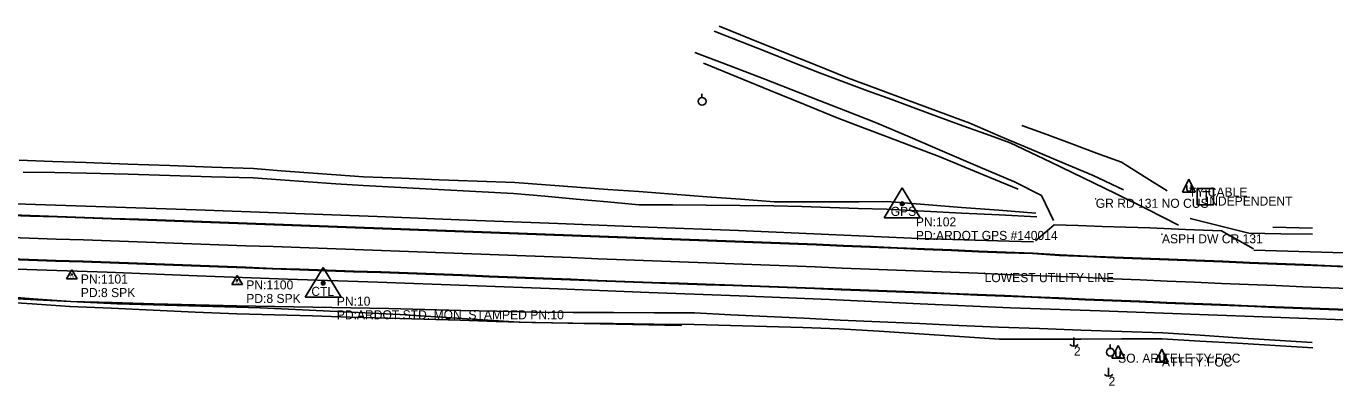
# Model space of a CAD drawing. Extents: x 878399 to 889864, y 1564003 to 1567413.
# Drawn here: x 887438 to 888162, y 1564366 to 1564564 of the extents above; entities that cross this region are included whole.
import ezdxf

# ---------------------------------------------------------------- set-up
doc = ezdxf.new("R2010")
doc.units = 0
for name, color, linetype in [('S_DITCHLINE', 7, 'Continuous'), ('S_DRIVEWAY', 7, 'Continuous'), ('S_EDGE_PAVEMENT', 7, 'Continuous'), ('S_ELECTRIC_UTILITIES_ANNOT', 7, 'Continuous'), ('S_FIBER_OPTIC_CABLE', 7, 'Continuous'), ('S_GRAVEL_ROAD', 7, 'Continuous'), ('S_MSC_PT_SYM', 7, 'Continuous'), ('S_PAVEMENT_CROWN', 7, 'Continuous'), ('S_PRIMARY_CTL', 7, 'Continuous'), ('S_PRIMARY_CTL_ANNOT', 7, 'Continuous'), ('S_SECONDARY_CTL', 7, 'Continuous'), ('S_SECONDARY_CTL_ANNOT', 7, 'Continuous'), ('S_SHOULDER', 7, 'Continuous'), ('S_SURVEY_TEXT_ANNOT', 7, 'Continuous'), ('S_TELEPHONE_UTILITIES', 7, 'Continuous'), ('S_TELEPHONE_UTILITIES_ANNOT', 7, 'Continuous'), ('S_UTILITY_POLE', 7, 'Continuous'), ('S_UTILITY_POLE_ANNOT', 7, 'Continuous'), ('S_UTL_PT_SYM', 7, 'Continuous')]:
    doc.layers.add(name, color=color, linetype=linetype)

msp = doc.modelspace()

# ---------------------------------------------------------------- linework, layer by layer
at = {"layer": 'S_DITCHLINE'}
for points in [[(888045.28, 1564473.95), (888028.58, 1564481.87), (888011.51, 1564489.1), (887994.45, 1564496.33), (887977.38, 1564503.55), (887960.32, 1564510.78), (887943.43, 1564517.06), (887926.53, 1564523.34), (887909.64, 1564529.63), (887892.75, 1564535.91), (887875.01, 1564543.04), (887857.27, 1564550.17), (887839.53, 1564557.3), (887821.79, 1564564.43)], [(887987.13, 1564474.32), (887965.23, 1564483.38), (887943.33, 1564492.43), (887929.25, 1564497.75), (887915.16, 1564503.07), (887901.08, 1564508.39), (887886.99, 1564513.72), (887868.5, 1564521.3), (887850.01, 1564528.88), (887831.51, 1564536.47), (887813.02, 1564544.05)], [(888069.44, 1564473.4), (888056.84, 1564481.33), (888044.24, 1564489.27), (888030.48, 1564494.36), (888016.72, 1564499.46), (888002.96, 1564504.56), (887989.2, 1564509.65)], [(887996.97, 1564461.15), (887976.39, 1564462.74), (887955.8, 1564464.33), (887935.22, 1564465.93), (887914.64, 1564467.52), (887899.07, 1564467.48), (887883.5, 1564467.45), (887867.93, 1564467.42), (887852.37, 1564467.39), (887833.62, 1564468.81), (887814.87, 1564470.23), (887796.12, 1564471.65), (887777.37, 1564473.08), (887760.23, 1564474.31), (887743.08, 1564475.55), (887725.94, 1564476.78), (887708.79, 1564478.01), (887687.87, 1564478.83), (887666.95, 1564479.64), (887646.02, 1564480.45), (887625.1, 1564481.26), (887609.89, 1564482.38), (887594.69, 1564483.5), (887579.48, 1564484.61), (887564.28, 1564485.73), (887541.1, 1564486.58), (887517.91, 1564487.43), (887494.73, 1564488.28), (887471.55, 1564489.14), (887453.1, 1564489.78), (887434.65, 1564490.42)], [(887997.43, 1564459.14), (887976.65, 1564460.18), (887955.88, 1564461.21), (887935.11, 1564462.25), (887914.34, 1564463.28), (887898.71, 1564463.77), (887883.08, 1564464.26), (887867.46, 1564464.75), (887851.83, 1564465.24), (887833.22, 1564465.39), (887814.62, 1564465.53), (887796.01, 1564465.68), (887777.4, 1564465.82), (887760.04, 1564467.38), (887742.68, 1564468.94), (887725.32, 1564470.5), (887707.96, 1564472.06), (887687.19, 1564473.13), (887666.42, 1564474.2), (887645.65, 1564475.27), (887624.88, 1564476.34), (887609.65, 1564477.4), (887594.43, 1564478.47), (887579.2, 1564479.53), (887563.98, 1564480.6), (887540.93, 1564481.27), (887517.88, 1564481.95), (887494.83, 1564482.63), (887471.77, 1564483.3), (887454.31, 1564483.52), (887436.85, 1564483.75)], [(888149.84, 1564449.49), (888132.3, 1564449.82), (888114.77, 1564450.16), (888098.52, 1564454.17), (888082.27, 1564458.18)], [(888149.86, 1564452.88), (888127.89, 1564453.46)], [(888150.12, 1564386.83), (888129.29, 1564388.05), (888108.46, 1564389.27), (888087.63, 1564390.49), (888066.79, 1564391.71), (888044.31, 1564391.66), (888021.82, 1564391.61), (887999.34, 1564391.56), (887976.85, 1564391.51), (887954.63, 1564392.96), (887932.41, 1564394.42), (887910.19, 1564395.87), (887887.96, 1564397.32), (887867.96, 1564397.9), (887847.96, 1564398.48), (887827.96, 1564399.07), (887807.96, 1564399.65), (887785.57, 1564399.91), (887763.17, 1564400.17), (887740.77, 1564400.43), (887718.37, 1564400.69), (887698.41, 1564401.32), (887678.45, 1564401.95), (887658.48, 1564402.58), (887638.52, 1564403.2), (887617.64, 1564403.77), (887596.75, 1564404.34), (887575.87, 1564404.91), (887554.98, 1564405.48), (887531.89, 1564406.52), (887508.79, 1564407.57), (887485.7, 1564408.61), (887462.6, 1564409.65), (887441.87, 1564411.02), (887421.14, 1564412.39)], [(888149.76, 1564389.68), (888129.08, 1564391.01), (888108.41, 1564392.34), (888087.73, 1564393.67), (888067.05, 1564394.99), (888044.37, 1564395.79), (888021.68, 1564396.58), (887998.99, 1564397.38), (887976.3, 1564398.17), (887954.38, 1564399.16), (887932.46, 1564400.14), (887910.54, 1564401.13), (887888.62, 1564402.12), (887868.5, 1564403.09), (887848.38, 1564404.07), (887828.26, 1564405.05), (887808.14, 1564406.02), (887785.77, 1564406.12), (887763.39, 1564406.22), (887741.02, 1564406.32), (887718.64, 1564406.42), (887698.72, 1564406.92), (887678.81, 1564407.41), (887658.89, 1564407.91), (887638.97, 1564408.4), (887617.98, 1564408.8), (887596.99, 1564409.2), (887576, 1564409.61), (887555.01, 1564410.01), (887532.03, 1564410.57), (887509.05, 1564411.14), (887486.07, 1564411.71), (887463.1, 1564412.28), (887442.27, 1564413.89), (887421.45, 1564415.51)]]:
    msp.add_lwpolyline(points, dxfattribs=at)
at = {"layer": 'S_DRIVEWAY'}
msp.add_lwpolyline([(888117.21, 1564441.53), (888099.57, 1564451.41), (888079.75, 1564452.18), (888059.93, 1564452.96), (888046.71, 1564453.41), (888033.48, 1564453.87), (888020.26, 1564454.32), (888007.04, 1564454.77), (887996.68, 1564445.93)], dxfattribs=at)
at = {"layer": 'S_EDGE_PAVEMENT'}
for points in [[(887425.87, 1564460.41), (887440.86, 1564459.9), (887455.84, 1564459.36), (887470.82, 1564458.82), (887485.8, 1564458.29), (887500.79, 1564457.76), (887515.77, 1564457.23), (887530.76, 1564456.71), (887545.74, 1564456.18), (887560.73, 1564455.65), (887575.72, 1564455.12), (887590.71, 1564454.57), (887590.71, 1564454.57), (887590.71, 1564454.57), (887605.69, 1564454.01), (887620.68, 1564453.45), (887635.74, 1564452.89), (887635.74, 1564452.89), (887635.74, 1564452.89), (887650.73, 1564452.32), (887665.72, 1564451.75), (887680.71, 1564451.19), (887695.7, 1564450.64), (887710.69, 1564450.09), (887725.68, 1564449.54), (887740.67, 1564448.97), (887755.66, 1564448.4), (887770.65, 1564447.82), (887785.64, 1564447.25), (887800.63, 1564446.7), (887815.62, 1564446.16), (887830.61, 1564445.61), (887830.61, 1564445.61), (887830.61, 1564445.61), (887845.6, 1564445.05), (887860.59, 1564444.49), (887875.58, 1564443.93), (887890.57, 1564443.33), (887905.41, 1564442.69), (887920.39, 1564442.05), (887935.38, 1564441.42), (887935.38, 1564441.42), (887935.38, 1564441.42), (887950.36, 1564440.81), (887965.35, 1564440.2), (887965.35, 1564440.2), (887965.35, 1564440.2), (887980.34, 1564439.59), (887995.33, 1564439.13), (888010.3, 1564438.09), (888025.43, 1564437.47), (888040.41, 1564436.85), (888055.39, 1564436.23), (888070.38, 1564435.66), (888085.36, 1564435.1), (888100.34, 1564434.54), (888115.32, 1564433.92), (888130.31, 1564433.32), (888145.29, 1564432.72), (888160.28, 1564432.13), (888175.26, 1564431.52)], [(887425.59, 1564460.07), (887440.58, 1564459.57), (887455.56, 1564459.03), (887470.54, 1564458.49), (887485.53, 1564457.95), (887500.51, 1564457.43), (887515.5, 1564456.9), (887530.48, 1564456.37), (887545.47, 1564455.84), (887560.46, 1564455.31), (887575.45, 1564454.78), (887590.43, 1564454.23), (887590.43, 1564454.23), (887590.43, 1564454.23), (887605.42, 1564453.68), (887620.41, 1564453.12), (887635.47, 1564452.55), (887635.47, 1564452.55), (887635.47, 1564452.55), (887650.46, 1564451.99), (887665.45, 1564451.42), (887680.44, 1564450.85), (887695.43, 1564450.3), (887710.42, 1564449.75), (887725.41, 1564449.2), (887740.41, 1564448.64), (887755.4, 1564448.06), (887770.39, 1564447.49), (887785.38, 1564446.92), (887800.37, 1564446.37), (887815.36, 1564445.82), (887830.35, 1564445.28), (887830.35, 1564445.28), (887830.35, 1564445.28), (887845.34, 1564444.72), (887860.33, 1564444.16), (887875.32, 1564443.6), (887890.31, 1564442.99), (887905.15, 1564442.36), (887920.14, 1564441.72), (887935.12, 1564441.08), (887935.12, 1564441.08), (887935.12, 1564441.08), (887950.11, 1564440.47), (887965.1, 1564439.87), (887965.1, 1564439.87), (887965.1, 1564439.87), (887980.09, 1564439.26), (887995.08, 1564438.79), (888010.05, 1564437.76), (888025.18, 1564437.13), (888040.16, 1564436.51), (888055.15, 1564435.89), (888070.13, 1564435.32), (888085.11, 1564434.77), (888100.1, 1564434.2), (888115.08, 1564433.58), (888130.06, 1564432.98), (888145.05, 1564432.39), (888160.03, 1564431.8), (888175.02, 1564431.18)], [(887424.76, 1564435.73), (887439.75, 1564435.22), (887454.73, 1564434.72), (887469.71, 1564434.22), (887484.7, 1564433.71), (887499.68, 1564433.15), (887514.67, 1564432.59), (887529.65, 1564432.02), (887544.64, 1564431.46), (887559.62, 1564430.89), (887574.61, 1564430.32), (887589.6, 1564429.79), (887604.59, 1564429.3), (887619.58, 1564428.81), (887634.46, 1564428.32), (887649.45, 1564427.76), (887664.43, 1564427.21), (887679.42, 1564426.65), (887694.41, 1564426.06), (887709.39, 1564425.46), (887724.38, 1564424.86), (887739.37, 1564424.27), (887754.36, 1564423.71), (887769.35, 1564423.14), (887784.34, 1564422.58), (887799.34, 1564422.09), (887814.33, 1564421.59), (887829.32, 1564421.1), (887844.31, 1564420.56), (887859.31, 1564420.01), (887874.3, 1564419.45), (887889.29, 1564418.88), (887904.44, 1564418.28), (887919.42, 1564417.68), (887934.41, 1564417.09), (887949.4, 1564416.5), (887964.39, 1564415.91), (887979.37, 1564415.32), (887979.37, 1564415.32), (887994.36, 1564414.67), (888009.34, 1564414), (888024.1, 1564413.34), (888039.09, 1564412.7), (888054.07, 1564412.1), (888069.05, 1564411.5), (888084.03, 1564410.9), (888099.02, 1564410.3), (888114, 1564409.7), (888128.99, 1564409.11), (888143.97, 1564408.53), (888158.96, 1564407.97), (888173.95, 1564407.4)], [(887425.04, 1564436.06), (887440.03, 1564435.55), (887455.01, 1564435.05), (887469.99, 1564434.55), (887484.98, 1564434.05), (887499.96, 1564433.48), (887514.94, 1564432.92), (887529.93, 1564432.36), (887544.91, 1564431.79), (887559.9, 1564431.23), (887574.88, 1564430.66), (887589.87, 1564430.12), (887604.86, 1564429.63), (887619.85, 1564429.14), (887634.73, 1564428.65), (887649.71, 1564428.1), (887664.7, 1564427.54), (887679.69, 1564426.99), (887694.68, 1564426.4), (887709.66, 1564425.79), (887724.64, 1564425.19), (887739.63, 1564424.61), (887754.62, 1564424.04), (887769.61, 1564423.48), (887784.6, 1564422.92), (887799.6, 1564422.42), (887814.59, 1564421.93), (887829.58, 1564421.44), (887844.57, 1564420.9), (887859.56, 1564420.34), (887874.55, 1564419.79), (887889.54, 1564419.22), (887904.69, 1564418.61), (887919.68, 1564418.02), (887934.67, 1564417.42), (887949.65, 1564416.83), (887964.64, 1564416.24), (887979.63, 1564415.65), (887979.63, 1564415.65), (887994.61, 1564415), (888009.59, 1564414.34), (888024.35, 1564413.68), (888039.33, 1564413.04), (888054.32, 1564412.44), (888069.3, 1564411.83), (888084.28, 1564411.23), (888099.26, 1564410.64), (888114.25, 1564410.04), (888129.23, 1564409.45), (888144.22, 1564408.87), (888159.2, 1564408.3), (888174.19, 1564407.73)]]:
    msp.add_lwpolyline(points, dxfattribs=at)
at = {"layer": 'S_FIBER_OPTIC_CABLE'}
for p, q in [((887488.84, 1564411.08), (887385.92, 1564416.28)), ((887567.98, 1564408.8), (887488.84, 1564411.08)), ((887645.2, 1564405.16), (887567.98, 1564408.8)), ((887711.2, 1564400.93), (887645.2, 1564405.16)), ((887800.68, 1564399.02), (887711.2, 1564400.93))]:
    msp.add_line(p, q, dxfattribs=at)
at = {"layer": 'S_GRAVEL_ROAD'}
for points in [[(887819.01, 1564561.74), (887833.59, 1564555.98), (887848.16, 1564550.22), (887862.73, 1564544.46), (887877.3, 1564538.7), (887890.59, 1564533.76), (887903.87, 1564528.81), (887917.15, 1564523.87), (887930.44, 1564518.92), (887943.5, 1564514.19), (887956.57, 1564509.46), (887969.63, 1564504.74), (887982.7, 1564500.01), (888005.16, 1564489.34), (888023.06, 1564480.65), (888040.96, 1564471.96), (888058.38, 1564463.28), (888075.79, 1564454.6)], [(888006.62, 1564457.12), (887999.98, 1564470.88), (887985.05, 1564478.45), (887965.82, 1564486.64), (887946.59, 1564494.84), (887927.37, 1564503.04), (887908.14, 1564511.23), (887892.63, 1564517.31), (887877.12, 1564523.39), (887861.61, 1564529.47), (887846.1, 1564535.55), (887827.23, 1564542.75), (887808.35, 1564549.96)]]:
    msp.add_lwpolyline(points, dxfattribs=at)
at = {"layer": 'S_MSC_PT_SYM'}
for points in [[(888030.01, 1564469.1), (888030.01, 1564469.15), (888030.01, 1564469.1), (888029.96, 1564469.1), (888030.01, 1564469.1), (888030.01, 1564469.05), (888030.01, 1564469.1), (888030.06, 1564469.1)], [(888066.66, 1564449.5), (888066.66, 1564449.55), (888066.66, 1564449.5), (888066.61, 1564449.5), (888066.66, 1564449.5), (888066.66, 1564449.45), (888066.66, 1564449.5), (888066.71, 1564449.5)]]:
    msp.add_lwpolyline(points, dxfattribs=at)
at = {"layer": 'S_PAVEMENT_CROWN'}
msp.add_lwpolyline([(887425.17, 1564447.82), (887440.15, 1564447.32), (887440.15, 1564447.32), (887455.14, 1564446.83), (887470.12, 1564446.34), (887485.11, 1564445.81), (887485.11, 1564445.81), (887500.09, 1564445.27), (887515.07, 1564444.74), (887530.06, 1564444.21), (887545.05, 1564443.68), (887560.03, 1564443.16), (887575.02, 1564442.64), (887590.01, 1564442.12), (887605, 1564441.6), (887605, 1564441.6), (887605, 1564441.6), (887619.99, 1564441.08), (887634.97, 1564440.52), (887649.95, 1564439.97), (887664.94, 1564439.41), (887664.94, 1564439.41), (887679.93, 1564438.85), (887694.92, 1564438.28), (887709.91, 1564437.71), (887724.9, 1564437.14), (887739.89, 1564436.57), (887754.88, 1564436), (887769.87, 1564435.43), (887784.87, 1564434.88), (887799.86, 1564434.34), (887814.85, 1564433.79), (887814.85, 1564433.79), (887829.84, 1564433.22), (887844.83, 1564432.62), (887859.82, 1564432.03), (887874.81, 1564431.44), (887889.8, 1564430.84), (887904.8, 1564430.24), (887919.78, 1564429.64), (887934.77, 1564429.07), (887949.76, 1564428.5), (887964.75, 1564427.94), (887979.74, 1564427.35), (887994.72, 1564426.74), (888009.71, 1564426.14), (888024.66, 1564425.53), (888039.64, 1564424.88), (888054.63, 1564424.24), (888069.61, 1564423.59), (888069.61, 1564423.59), (888084.59, 1564422.97), (888099.57, 1564422.35), (888114.55, 1564421.73), (888129.53, 1564421.12), (888144.52, 1564420.52), (888159.5, 1564419.92), (888174.49, 1564419.32)], dxfattribs=at)
at = {"layer": 'S_PRIMARY_CTL'}
for p, q in [((887923.03, 1564475.05), (887913, 1564458.54)), ((887923.03, 1564475.05), (887932.86, 1564458.54)), ((887913, 1564458.54), (887932.86, 1564458.54)), ((887602.77, 1564431.21), (887592.74, 1564414.7)), ((887602.77, 1564431.21), (887612.6, 1564414.7)), ((887592.74, 1564414.7), (887612.6, 1564414.7))]:
    msp.add_line(p, q, dxfattribs=at)
for centre, radius in [((887923.03, 1564466.35), 1.04), ((887923.03, 1564466.35), 0.609), ((887923.03, 1564466.35), 0.344), ((887602.77, 1564422.51), 1.04), ((887602.77, 1564422.51), 0.609), ((887602.77, 1564422.51), 0.344)]:
    msp.add_circle(centre, radius, dxfattribs=at)
at = {"layer": 'S_SECONDARY_CTL'}
for p, q in [((887463.7, 1564429.89), (887460.69, 1564424.93)), ((887460.69, 1564424.93), (887466.64, 1564424.93)), ((887463.7, 1564429.89), (887466.64, 1564424.93)), ((887555.18, 1564426.63), (887552.17, 1564421.67)), ((887555.18, 1564426.63), (887558.13, 1564421.67)), ((887552.17, 1564421.67), (887558.13, 1564421.67))]:
    msp.add_line(p, q, dxfattribs=at)
for centre, radius in [((887463.7, 1564427.28), 0.311), ((887463.7, 1564427.28), 0.183), ((887463.7, 1564427.28), 0.103), ((887555.18, 1564424.02), 0.311), ((887555.18, 1564424.02), 0.183), ((887555.18, 1564424.02), 0.103)]:
    msp.add_circle(centre, radius, dxfattribs=at)
at = {"layer": 'S_SHOULDER'}
for points in [[(887432.62, 1564466.36), (887482.58, 1564464.72), (887532.54, 1564463.02), (887582.49, 1564461.17), (887632.56, 1564459.3), (887682.52, 1564457.21), (887732.49, 1564455.38), (887782.46, 1564453.45), (887832.43, 1564451.58), (887882.38, 1564449.27), (887932.12, 1564447.23), (887982.09, 1564445.67), (887995.68, 1564445.27)], [(888117.39, 1564440.68), (888167.36, 1564439.21), (888217.28, 1564436.98), (888267.1, 1564434.9), (888317.04, 1564432.5), (888367.01, 1564430.86), (888416.96, 1564428.63), (888466.91, 1564426.26), (888516.87, 1564424.37), (888566.86, 1564422.28), (888616.84, 1564420.55), (888666.8, 1564418.53), (888716.75, 1564416.33), (888766.68, 1564414.1), (888816.64, 1564411.92), (888866.6, 1564409.9), (888916.63, 1564407.74), (888966.59, 1564405.72), (889016.56, 1564403.83), (889066.51, 1564401.85), (889116.48, 1564399.99), (889166.44, 1564398.04), (889198.47, 1564396.92)], [(887433.22, 1564430.22), (887483.18, 1564428.56), (887533.13, 1564426.59), (887583.07, 1564424.7), (887632.88, 1564423.07), (887682.85, 1564421.26), (887732.8, 1564419.26), (887782.77, 1564417.37), (887832.74, 1564415.45), (887882.7, 1564413.51), (887932.89, 1564411.06), (887982.84, 1564408.85), (888032.5, 1564407.28), (888082.44, 1564405.27), (888132.4, 1564403.53), (888182.36, 1564401.64)]]:
    msp.add_lwpolyline(points, dxfattribs=at)
at = {"layer": 'S_TELEPHONE_UTILITIES'}
msp.add_lwpolyline([(888086.18, 1564465.82), (888086.18, 1564474.82), (888095.18, 1564474.82), (888095.18, 1564465.82)], close=True, dxfattribs=at)
at = {"layer": 'S_UTILITY_POLE'}
for p, q in [((887812.22, 1564525.05), (887812.22, 1564527.15)), ((888081.55, 1564479.85), (888078.03, 1564472.76)), ((888080.35, 1564474), (888080.35, 1564476.44)), ((888081.55, 1564479.85), (888085.04, 1564472.76)), ((888082.72, 1564476.44), (888082.72, 1564474)), ((888078.03, 1564472.76), (888085.04, 1564472.76)), ((888080.97, 1564473.34), (888080.35, 1564474)), ((888082.17, 1564473.34), (888080.97, 1564473.34)), ((888082.72, 1564474), (888082.17, 1564473.34)), ((888017.93, 1564392.4), (888017.93, 1564387.67)), ((888037.96, 1564386.48), (888037.96, 1564388.59)), ((888042.4, 1564388.06), (888038.87, 1564380.97)), ((888042.4, 1564388.06), (888045.88, 1564380.97)), ((888038.87, 1564380.97), (888045.88, 1564380.97)), ((888041.2, 1564382.21), (888041.2, 1564384.65)), ((888041.82, 1564381.55), (888041.2, 1564382.21)), ((888043.02, 1564381.55), (888041.82, 1564381.55)), ((888043.56, 1564382.21), (888043.02, 1564381.55)), ((888043.56, 1564384.65), (888043.56, 1564382.21)), ((888066.62, 1564385.98), (888063.09, 1564378.89)), ((888065.42, 1564380.13), (888065.42, 1564382.57)), ((888066.62, 1564385.98), (888070.11, 1564378.89)), ((888067.78, 1564382.57), (888067.78, 1564380.13)), ((888037.08, 1564375.72), (888037.08, 1564370.99)), ((888063.09, 1564378.89), (888070.11, 1564378.89)), ((888066.04, 1564379.47), (888065.42, 1564380.13)), ((888067.24, 1564379.47), (888066.04, 1564379.47)), ((888067.78, 1564380.13), (888067.24, 1564379.47))]:
    msp.add_line(p, q, dxfattribs=at)
for centre in [(887812.34, 1564522.9), (888038.08, 1564384.34)]:
    msp.add_circle(centre, 2.13, dxfattribs=at)
for centre in [(888017.99, 1564391.1), (888037.14, 1564374.42)]:
    msp.add_arc(centre, 3.41, 226.39718, 313.60282, dxfattribs=at)
at = {"layer": 'S_UTL_PT_SYM'}
for points in [[(887968.55, 1564428.03), (887968.55, 1564428.08), (887968.55, 1564428.03), (887968.5, 1564428.03), (887968.55, 1564428.03), (887968.55, 1564427.98), (887968.55, 1564428.03), (887968.6, 1564428.03)], [(887488.84, 1564411.08), (887488.84, 1564411.13), (887488.84, 1564411.08), (887488.79, 1564411.08), (887488.84, 1564411.08), (887488.84, 1564411.03), (887488.84, 1564411.08), (887488.89, 1564411.08)], [(887567.98, 1564408.8), (887567.98, 1564408.85), (887567.98, 1564408.8), (887567.93, 1564408.8), (887567.98, 1564408.8), (887567.98, 1564408.75), (887567.98, 1564408.8), (887568.03, 1564408.8)], [(887645.2, 1564405.16), (887645.2, 1564405.21), (887645.2, 1564405.16), (887645.15, 1564405.16), (887645.2, 1564405.16), (887645.2, 1564405.11), (887645.2, 1564405.16), (887645.25, 1564405.16)], [(887711.2, 1564400.93), (887711.2, 1564400.98), (887711.2, 1564400.93), (887711.15, 1564400.93), (887711.2, 1564400.93), (887711.2, 1564400.88), (887711.2, 1564400.93), (887711.25, 1564400.93)], [(887800.68, 1564399.02), (887800.68, 1564399.07), (887800.68, 1564399.02), (887800.63, 1564399.02), (887800.68, 1564399.02), (887800.68, 1564398.97), (887800.68, 1564399.02), (887800.73, 1564399.02)]]:
    msp.add_lwpolyline(points, dxfattribs=at)

# ---------------------------------------------------------------- texts
at = {"layer": 'S_ELECTRIC_UTILITIES_ANNOT'}
msp.add_text('LOWEST UTILITY LINE', height=5, dxfattribs=at).set_placement((887968.55, 1564423.03))
at = {"layer": 'S_PRIMARY_CTL'}
for s, p in [('GPS', (887916.6, 1564459.64)), ('CTL', (887596.18, 1564415.44))]:
    msp.add_text(s, height=5, rotation=360, dxfattribs=at).set_placement(p)
at = {"layer": 'S_PRIMARY_CTL_ANNOT'}
for s, p in [('PN:102', (887930.53, 1564453.85)), ('PD:ARDOT GPS #140014', (887930.53, 1564446.35)), ('PN:10', (887610.27, 1564410.01)), ('PD:ARDOT STD. MON. STAMPED PN:10', (887610.27, 1564402.51))]:
    msp.add_text(s, height=5, dxfattribs=at).set_placement(p)
at = {"layer": 'S_SECONDARY_CTL'}
for p in [(887462.49, 1564425.27), (887553.98, 1564422.01)]:
    msp.add_text('TV', height=1.5, rotation=360, dxfattribs=at).set_placement(p)
at = {"layer": 'S_SECONDARY_CTL_ANNOT'}
for s, p in [('PN:1101', (887468.7, 1564422.28)), ('PD:8 SPK', (887468.7, 1564414.78)), ('PN:1100', (887560.19, 1564419.02)), ('PD:8 SPK', (887560.19, 1564411.52))]:
    msp.add_text(s, height=5, dxfattribs=at).set_placement(p)
at = {"layer": 'S_SURVEY_TEXT_ANNOT'}
for s, p in [('GR RD 131 NO CUS', (888030.01, 1564464.1)), ('ASPH DW CR 131', (888066.66, 1564444.5))]:
    msp.add_text(s, height=5, dxfattribs=at).set_placement(p)
at = {"layer": 'S_TELEPHONE_UTILITIES'}
msp.add_text('T', height=6, rotation=360, dxfattribs=at).set_placement((888088.74, 1564467.32))
at = {"layer": 'S_TELEPHONE_UTILITIES_ANNOT'}
msp.add_text('INDEPENDENT', height=5, dxfattribs=at).set_placement((888090.9, 1564465.34))
at = {"layer": 'S_UTILITY_POLE_ANNOT'}
for s, p in [('TY:CABLE', (888081.55, 1564470.32)), ('2', (888017.94, 1564382.46)), ('SO. AR TELE TY:FOC', (888042.4, 1564378.53)), ('ATT TY:FOC', (888066.62, 1564376.44)), ('2', (888037.09, 1564365.78))]:
    msp.add_text(s, height=5, dxfattribs=at).set_placement(p)

doc.saveas('drawing.dxf')
